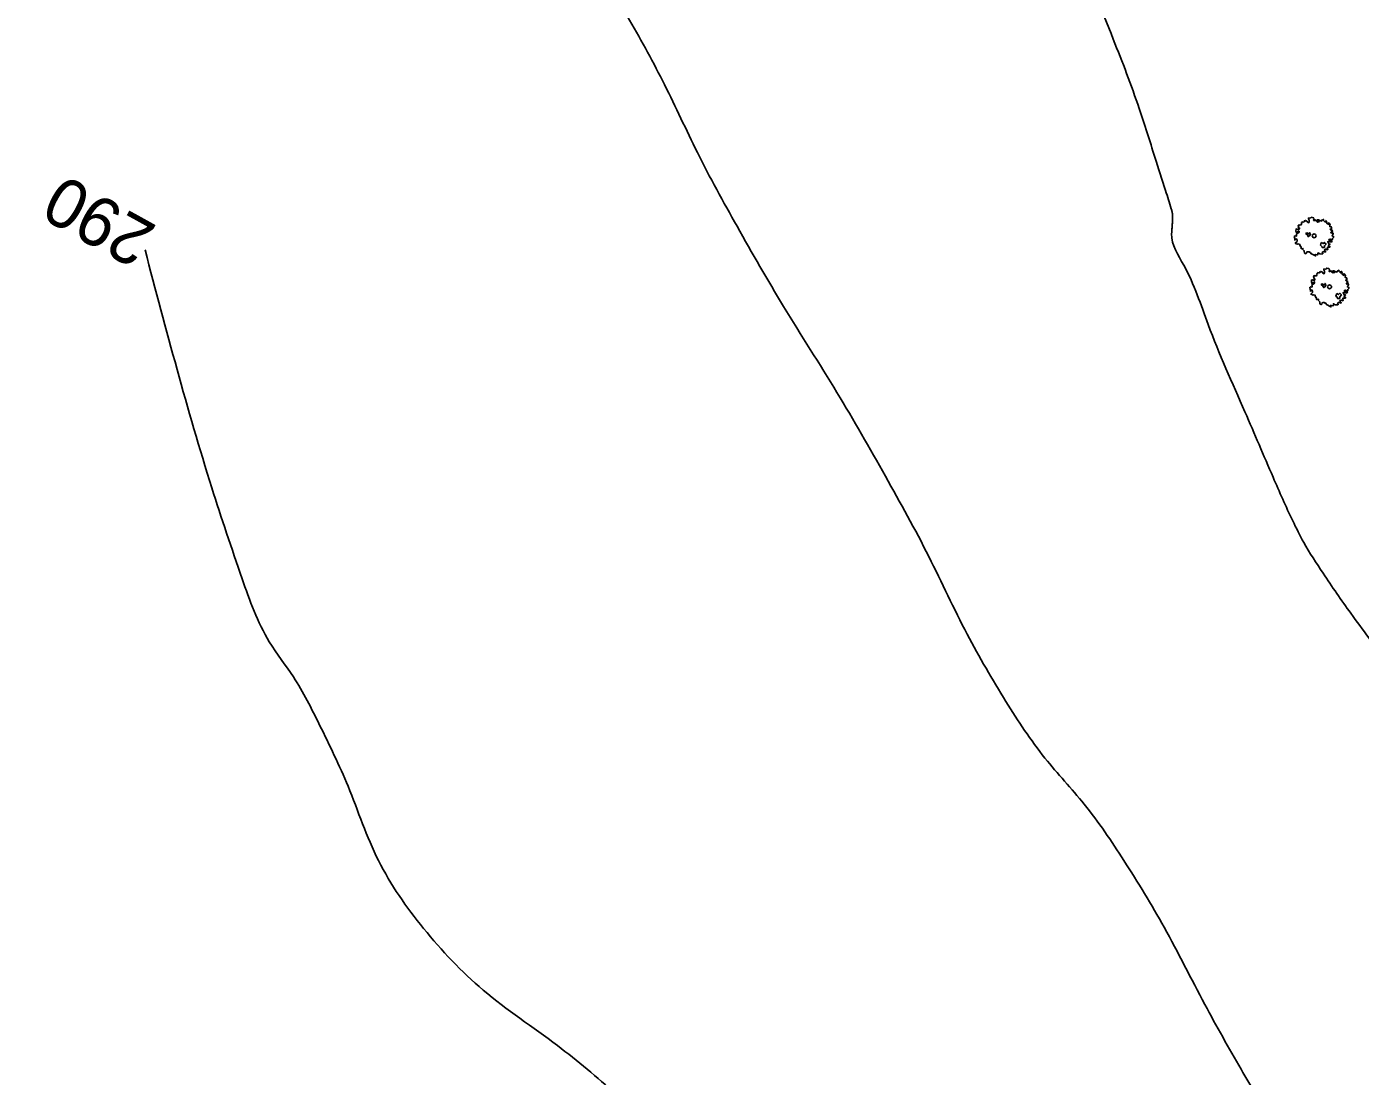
# Model space of a CAD drawing. Extents: x -478464 to -472469, y -1120963 to -1113785.
# Drawn here: x -477489.2 to -477380.7, y -1115869.6 to -1115784.3 of the extents above; entities that cross this region are included whole.
import ezdxf

# ---------------------------------------------------------------- set-up
doc = ezdxf.new("R2010")
doc.units = 0
for name, color, linetype in [('IP', 7, 'Continuous'), ('Vrstevnice_hlavni', 7, 'Continuous'), ('Vrstevnice_popis', 7, 'Continuous'), ('Vrstevnice_vedlejsi', 7, 'Continuous')]:
    doc.layers.add(name, color=color, linetype=linetype)

msp = doc.modelspace()

# ---------------------------------------------------------------- linework, layer by layer
at = {"layer": 'IP'}
for points in [[(-477383.58, -1115800.021), (-477383.485, -1115800.094), (-477383.507, -1115800.177), (-477383.448, -1115800.289), (-477383.314, -1115800.351), (-477383.357, -1115800.241), (-477383.306, -1115800.226), (-477383.191, -1115800.35), (-477383.214, -1115800.343), (-477383.223, -1115800.532), (-477383.106, -1115800.546), (-477383.081, -1115800.628), (-477383.095, -1115800.704), (-477383.162, -1115800.72), (-477383.181, -1115800.765), (-477383.084, -1115800.863), (-477383.07, -1115800.784), (-477383.011, -1115800.875), (-477383.034, -1115800.961), (-477383.133, -1115800.994), (-477383.102, -1115801.054), (-477382.979, -1115801.027), (-477382.944, -1115801.087), (-477382.981, -1115801.174), (-477383.057, -1115801.247), (-477382.921, -1115801.33), (-477382.923, -1115801.408), (-477383.014, -1115801.491), (-477383.005, -1115801.59), (-477383.074, -1115801.606), (-477383.196, -1115801.547), (-477383.289, -1115801.578), (-477383.273, -1115801.68), (-477383.186, -1115801.734), (-477383.193, -1115801.68), (-477383.149, -1115801.656), (-477383.092, -1115801.645), (-477383.045, -1115801.743), (-477383.087, -1115801.8), (-477383.231, -1115801.78), (-477383.281, -1115801.748), (-477383.404, -1115801.765), (-477383.391, -1115801.771), (-477383.301, -1115801.93), (-477383.196, -1115801.944), (-477383.317, -1115802.023), (-477383.293, -1115802.1), (-477383.207, -1115802.136), (-477383.209, -1115802.199), (-477383.418, -1115802.209), (-477383.422, -1115802.312), (-477383.364, -1115802.361), (-477383.469, -1115802.421), (-477383.513, -1115802.357), (-477383.6, -1115802.377), (-477383.653, -1115802.456), (-477383.561, -1115802.551), (-477383.561, -1115802.607), (-477383.647, -1115802.594), (-477383.692, -1115802.564), (-477383.77, -1115802.568), (-477383.839, -1115802.621), (-477383.789, -1115802.723), (-477383.831, -1115802.762), (-477384.03, -1115802.741), (-477384.177, -1115802.662), (-477384.215, -1115802.836), (-477384.349, -1115802.8), (-477384.443, -1115802.811), (-477384.383, -1115802.919), (-477384.753, -1115802.727), (-477384.798, -1115802.623), (-477384.881, -1115802.619), (-477384.898, -1115802.571), (-477385.014, -1115802.569), (-477385.102, -1115802.586), (-477385.121, -1115802.687), (-477385.177, -1115802.732), (-477385.277, -1115802.68), (-477385.297, -1115802.498), (-477385.43, -1115802.369), (-477385.392, -1115802.297), (-477385.549, -1115802.326), (-477385.559, -1115802.169), (-477385.616, -1115802.151), (-477385.657, -1115802.007), (-477385.656, -1115801.973), (-477385.804, -1115801.933), (-477385.847, -1115801.958), (-477385.948, -1115801.92), (-477386.029, -1115801.869), (-477385.878, -1115801.734), (-477385.874, -1115801.627), (-477385.917, -1115801.536), (-477385.987, -1115801.558), (-477386.056, -1115801.64), (-477386.075, -1115801.487), (-477386.113, -1115801.329), (-477386.051, -1115801.273), (-477385.93, -1115801.299), (-477385.918, -1115801.22), (-477385.938, -1115801.123), (-477385.773, -1115801.038), (-477385.71, -1115800.964), (-477385.722, -1115800.904), (-477385.784, -1115800.953), (-477385.858, -1115800.953), (-477385.944, -1115801.007), (-477385.979, -1115800.895), (-477385.969, -1115800.733), (-477385.892, -1115800.702), (-477385.827, -1115800.78), (-477385.757, -1115800.805), (-477385.691, -1115800.67), (-477385.684, -1115800.647), (-477385.784, -1115800.646), (-477385.746, -1115800.571), (-477385.775, -1115800.523), (-477385.803, -1115800.44), (-477385.745, -1115800.374), (-477385.679, -1115800.403), (-477385.564, -1115800.392), (-477385.535, -1115800.303), (-477385.547, -1115800.248), (-477385.446, -1115800.192), (-477385.472, -1115800.132), (-477385.34, -1115800.159), (-477385.282, -1115800.126), (-477385.285, -1115800.059), (-477385.198, -1115800.03), (-477385.189, -1115800.075), (-477385.137, -1115800.071), (-477385.081, -1115800.088), (-477385.059, -1115800.113), (-477385.049, -1115800.155), (-477385.022, -1115800.194), (-477384.987, -1115800.22), (-477384.934, -1115800.205), (-477384.911, -1115800.141), (-477384.91, -1115799.999), (-477384.957, -1115799.89), (-477384.952, -1115799.823), (-477384.835, -1115799.843), (-477384.751, -1115799.814), (-477384.731, -1115799.764), (-477384.557, -1115799.804), (-477384.542, -1115799.847), (-477384.503, -1115799.908), (-477384.538, -1115800.035), (-477384.475, -1115800.04), (-477384.375, -1115799.984), (-477384.312, -1115800.085), (-477384.206, -1115800.155), (-477384.076, -1115800.128), (-477384.239, -1115799.985), (-477384.152, -1115799.977), (-477383.91, -1115800.091), (-477383.858, -1115800.004), (-477383.749, -1115799.94), (-477383.72, -1115799.953), (-477383.751, -1115800.019), (-477383.618, -1115800.15), (-477383.556, -1115800.122)], [(-477385.05, -1115801.13), (-477385.05, -1115801.221), (-477384.967, -1115801.351), (-477384.87, -1115801.289), (-477384.789, -1115801.176), (-477384.867, -1115801.01), (-477384.887, -1115801.122), (-477384.952, -1115801.111), (-477385.014, -1115801.066), (-477385.041, -1115801.047), (-477385.161, -1115801.061), (-477385.154, -1115801.122), (-477385.121, -1115801.17), (-477385.075, -1115801.151)], [(-477383.916, -1115801.825), (-477383.989, -1115802.035), (-477383.822, -1115802.19), (-477383.853, -1115802.224), (-477383.667, -1115802.228), (-477383.664, -1115802.087), (-477383.53, -1115801.945), (-477383.672, -1115801.811), (-477383.774, -1115801.92), (-477383.841, -1115801.857)], [(-477382.326, -1115804.163), (-477382.23, -1115804.236), (-477382.252, -1115804.318), (-477382.194, -1115804.431), (-477382.06, -1115804.492), (-477382.102, -1115804.383), (-477382.052, -1115804.368), (-477381.937, -1115804.492), (-477381.959, -1115804.484), (-477381.968, -1115804.674), (-477381.852, -1115804.687), (-477381.827, -1115804.77), (-477381.841, -1115804.846), (-477381.908, -1115804.862), (-477381.927, -1115804.907), (-477381.83, -1115805.005), (-477381.816, -1115804.926), (-477381.757, -1115805.017), (-477381.78, -1115805.103), (-477381.878, -1115805.135), (-477381.848, -1115805.196), (-477381.724, -1115805.169), (-477381.689, -1115805.229), (-477381.727, -1115805.316), (-477381.802, -1115805.389), (-477381.666, -1115805.471), (-477381.669, -1115805.55), (-477381.76, -1115805.633), (-477381.751, -1115805.732), (-477381.82, -1115805.747), (-477381.942, -1115805.689), (-477382.035, -1115805.72), (-477382.019, -1115805.822), (-477381.931, -1115805.876), (-477381.938, -1115805.822), (-477381.895, -1115805.798), (-477381.837, -1115805.786), (-477381.791, -1115805.884), (-477381.832, -1115805.941), (-477381.977, -1115805.922), (-477382.027, -1115805.89), (-477382.149, -1115805.907), (-477382.136, -1115805.912), (-477382.046, -1115806.072), (-477381.942, -1115806.085), (-477382.062, -1115806.164), (-477382.038, -1115806.242), (-477381.953, -1115806.278), (-477381.955, -1115806.34), (-477382.164, -1115806.351), (-477382.168, -1115806.453), (-477382.11, -1115806.503), (-477382.214, -1115806.563), (-477382.258, -1115806.498), (-477382.346, -1115806.519), (-477382.398, -1115806.598), (-477382.307, -1115806.693), (-477382.306, -1115806.749), (-477382.393, -1115806.736), (-477382.438, -1115806.706), (-477382.516, -1115806.709), (-477382.584, -1115806.763), (-477382.535, -1115806.865), (-477382.577, -1115806.903), (-477382.776, -1115806.882), (-477382.923, -1115806.804), (-477382.961, -1115806.977), (-477383.095, -1115806.942), (-477383.189, -1115806.953), (-477383.129, -1115807.061), (-477383.499, -1115806.869), (-477383.543, -1115806.765), (-477383.626, -1115806.761), (-477383.644, -1115806.713), (-477383.76, -1115806.711), (-477383.848, -1115806.728), (-477383.867, -1115806.828), (-477383.922, -1115806.873), (-477384.022, -1115806.822), (-477384.043, -1115806.64), (-477384.176, -1115806.511), (-477384.138, -1115806.439), (-477384.294, -1115806.467), (-477384.305, -1115806.31), (-477384.362, -1115806.293), (-477384.402, -1115806.149), (-477384.402, -1115806.115), (-477384.55, -1115806.075), (-477384.593, -1115806.1), (-477384.694, -1115806.062), (-477384.775, -1115806.01), (-477384.623, -1115805.876), (-477384.619, -1115805.769), (-477384.663, -1115805.677), (-477384.733, -1115805.7), (-477384.801, -1115805.782), (-477384.821, -1115805.629), (-477384.859, -1115805.47), (-477384.797, -1115805.415), (-477384.676, -1115805.441), (-477384.664, -1115805.361), (-477384.684, -1115805.265), (-477384.519, -1115805.179), (-477384.456, -1115805.106), (-477384.467, -1115805.046), (-477384.53, -1115805.095), (-477384.603, -1115805.095), (-477384.69, -1115805.149), (-477384.725, -1115805.037), (-477384.715, -1115804.875), (-477384.638, -1115804.844), (-477384.572, -1115804.921), (-477384.502, -1115804.947), (-477384.437, -1115804.812), (-477384.43, -1115804.789), (-477384.529, -1115804.788), (-477384.492, -1115804.712), (-477384.521, -1115804.665), (-477384.548, -1115804.582), (-477384.49, -1115804.516), (-477384.424, -1115804.545), (-477384.31, -1115804.534), (-477384.281, -1115804.445), (-477384.293, -1115804.39), (-477384.191, -1115804.333), (-477384.218, -1115804.273), (-477384.086, -1115804.301), (-477384.027, -1115804.268), (-477384.03, -1115804.201), (-477383.944, -1115804.172), (-477383.935, -1115804.217), (-477383.882, -1115804.213), (-477383.826, -1115804.229), (-477383.804, -1115804.254), (-477383.795, -1115804.297), (-477383.768, -1115804.335), (-477383.733, -1115804.362), (-477383.679, -1115804.346), (-477383.656, -1115804.283), (-477383.656, -1115804.141), (-477383.703, -1115804.032), (-477383.697, -1115803.965), (-477383.58, -1115803.985), (-477383.497, -1115803.956), (-477383.477, -1115803.906), (-477383.302, -1115803.945), (-477383.288, -1115803.989), (-477383.248, -1115804.05), (-477383.284, -1115804.176), (-477383.22, -1115804.181), (-477383.12, -1115804.125), (-477383.058, -1115804.227), (-477382.951, -1115804.297), (-477382.821, -1115804.269), (-477382.985, -1115804.126), (-477382.898, -1115804.119), (-477382.656, -1115804.232), (-477382.603, -1115804.146), (-477382.495, -1115804.082), (-477382.466, -1115804.095), (-477382.497, -1115804.161), (-477382.363, -1115804.292), (-477382.302, -1115804.264)], [(-477383.796, -1115805.271), (-477383.796, -1115805.363), (-477383.713, -1115805.492), (-477383.616, -1115805.43), (-477383.534, -1115805.318), (-477383.613, -1115805.151), (-477383.632, -1115805.264), (-477383.698, -1115805.253), (-477383.76, -1115805.208), (-477383.786, -1115805.188), (-477383.907, -1115805.203), (-477383.899, -1115805.263), (-477383.867, -1115805.312), (-477383.821, -1115805.293)], [(-477382.662, -1115805.966), (-477382.735, -1115806.177), (-477382.567, -1115806.331), (-477382.599, -1115806.365), (-477382.413, -1115806.37), (-477382.41, -1115806.229), (-477382.276, -1115806.087), (-477382.418, -1115805.953), (-477382.52, -1115806.061), (-477382.587, -1115805.999)]]:
    msp.add_lwpolyline(points, close=True, dxfattribs=at)
for centre in [(-477384.497, -1115801.283), (-477383.243, -1115805.425)]:
    msp.add_circle(centre, 0.158, dxfattribs=at)
at = {"layer": 'Vrstevnice_hlavni'}
msp.add_spline([(-477334.231, -1115993.767), (-477348.086, -1115974.579), (-477353.101, -1115967.63), (-477356.202, -1115963.324), (-477357.39, -1115961.662), (-477358.34, -1115960.372), (-477359.052, -1115959.453), (-477359.526, -1115958.907), (-477362.084, -1115956.522), (-477366.726, -1115952.3), (-477373.452, -1115946.239), (-477379.296, -1115939.957), (-477384.258, -1115933.452), (-477388.338, -1115926.726), (-477391.356, -1115921.698), (-477393.313, -1115918.368), (-477394.208, -1115916.735), (-477395.349, -1115914.754), (-477396.737, -1115912.425), (-477398.372, -1115909.747), (-477403.163, -1115904.953), (-477411.112, -1115898.043), (-477422.219, -1115889.018), (-477430.365, -1115882.071), (-477435.55, -1115877.203), (-477437.775, -1115874.413), (-477441.27, -1115871.051), (-477446.035, -1115867.117), (-477452.07, -1115862.611), (-477456.921, -1115857.596), (-477460.587, -1115852.07), (-477463.068, -1115846.035), (-477465.376, -1115841.059), (-477467.509, -1115837.142), (-477469.467, -1115834.284), (-477471.678, -1115829.157), (-477474.142, -1115821.76), (-477479.574, -1115802.43)], degree=3, dxfattribs=at)
at = {"layer": 'Vrstevnice_vedlejsi'}
for points in [[(-477535.93, -1115532.82), (-477534.231, -1115534.826), (-477529.55, -1115540.603), (-477524.775, -1115546.882), (-477521.239, -1115551.827), (-477518.943, -1115555.44), (-477517.886, -1115557.72), (-477517.005, -1115559.768), (-477516.301, -1115561.585), (-477515.773, -1115563.17), (-477514.249, -1115568.143), (-477511.731, -1115576.504), (-477508.218, -1115588.252), (-477503.131, -1115599.263), (-477496.47, -1115609.538), (-477488.235, -1115619.076), (-477482.234, -1115626.134), (-477478.468, -1115630.712), (-477476.937, -1115632.811), (-477475.949, -1115634.309), (-477475.506, -1115635.207), (-477475.606, -1115635.504), (-477475.009, -1115636.168), (-477473.714, -1115637.2), (-477471.722, -1115638.6), (-477467.091, -1115642.447), (-477459.82, -1115648.74), (-477449.91, -1115657.48), (-477441.655, -1115664.837), (-477435.056, -1115670.813), (-477430.112, -1115675.407), (-477426.12, -1115679.408), (-477423.08, -1115682.818), (-477420.993, -1115685.636), (-477418.264, -1115689.357), (-477414.894, -1115693.981), (-477410.881, -1115699.507), (-477407.419, -1115704.78), (-477404.507, -1115709.801), (-477402.145, -1115714.569), (-477400.568, -1115717.748), (-477399.774, -1115719.338), (-477399.764, -1115719.338), (-477399.751, -1115719.361), (-477399.735, -1115719.406), (-477399.716, -1115719.475), (-477399.696, -1115719.545), (-477399.675, -1115719.618), (-477399.654, -1115719.693), (-477399.629, -1115719.768), (-477399.599, -1115719.845), (-477399.566, -1115719.922), (-477399.526, -1115720.024), (-477399.48, -1115720.149), (-477399.428, -1115720.299), (-477397.485, -1115724.164), (-477393.652, -1115731.746), (-477387.928, -1115743.044), (-477383.476, -1115752.353), (-477380.296, -1115759.674), (-477378.386, -1115765.008), (-477376.582, -1115770.037), (-477374.882, -1115774.763), (-477373.286, -1115779.185), (-477372.202, -1115782.353), (-477371.628, -1115784.267), (-477371.566, -1115784.927), (-477371.519, -1115785.601), (-477371.488, -1115786.291), (-477371.473, -1115786.997), (-477371.503, -1115787.551), (-477371.579, -1115787.953), (-477371.701, -1115788.205), (-477371.905, -1115788.793), (-477372.19, -1115789.717), (-477372.558, -1115790.978), (-477373.011, -1115792.65), (-477373.549, -1115794.733), (-477374.173, -1115797.226), (-477374.607, -1115798.989), (-477374.851, -1115800.019), (-477374.905, -1115800.319), (-477374.939, -1115800.599), (-477374.955, -1115800.858)], [(-477287.632, -1116051.539), (-477286.32, -1116047.536), (-477285.638, -1116044.105), (-477285.587, -1116041.246), (-477286.167, -1116038.959), (-477287.659, -1116036.397), (-477290.063, -1116033.561), (-477293.379, -1116030.449), (-477295.283, -1116025.963), (-477295.775, -1116020.104), (-477294.854, -1116012.871), (-477293.825, -1116007.495), (-477292.688, -1116003.976), (-477291.442, -1116002.315), (-477290.445, -1115998.859), (-477289.699, -1115993.611), (-477289.202, -1115986.569), (-477288.676, -1115980.878), (-477288.121, -1115976.537), (-477287.537, -1115973.548), (-477287.201, -1115971.521), (-477287.115, -1115970.456), (-477287.276, -1115970.354), (-477288.335, -1115969.099), (-477290.29, -1115966.689), (-477293.142, -1115963.125), (-477296.708, -1115959.125), (-477300.986, -1115954.688), (-477305.978, -1115949.815), (-477309.475, -1115946.392), (-477311.478, -1115944.42), (-477311.987, -1115943.899), (-477313.16, -1115942.38), (-477314.997, -1115939.862), (-477317.498, -1115936.346), (-477320.422, -1115932.577), (-477323.768, -1115928.554), (-477327.536, -1115924.277), (-477331.317, -1115918.9), (-477335.113, -1115912.423), (-477338.922, -1115904.846), (-477342.49, -1115897.876), (-477345.815, -1115891.512), (-477348.9, -1115885.756), (-477351.846, -1115880.306), (-477354.656, -1115875.16), (-477357.328, -1115870.321), (-477360.247, -1115865.399), (-477363.413, -1115860.395), (-477366.825, -1115855.308), (-477369.7, -1115850.782), (-477372.037, -1115846.815), (-477373.837, -1115843.407), (-477376.016, -1115839.798), (-477378.575, -1115835.985), (-477381.514, -1115831.971), (-477383.772, -1115828.71), (-477385.347, -1115826.203), (-477386.24, -1115824.45), (-477387.833, -1115820.914), (-477390.124, -1115815.596), (-477393.114, -1115808.495), (-477395.102, -1115803.67), (-477396.086, -1115801.12), (-477396.068, -1115800.846), (-477396.049, -1115800.554), (-477396.029, -1115800.243), (-477396.007, -1115799.914), (-477396.014, -1115799.611), (-477396.048, -1115799.335), (-477396.111, -1115799.086), (-477396.578, -1115797.601), (-477397.449, -1115794.879), (-477398.725, -1115790.921), (-477400.833, -1115785.286), (-477403.776, -1115777.975), (-477407.552, -1115768.988), (-477412.65, -1115759.156), (-477419.071, -1115748.481), (-477426.814, -1115736.962), (-477432.395, -1115728.678), (-477435.814, -1115723.629), (-477437.071, -1115721.814), (-477437.943, -1115720.536), (-477438.43, -1115719.794), (-477438.532, -1115719.589), (-477438.752, -1115719.242), (-477439.089, -1115718.756), (-477439.545, -1115718.129), (-477443.189, -1115713.546), (-477450.023, -1115705.007), (-477460.046, -1115692.512), (-477467.831, -1115683.216), (-477473.377, -1115677.119), (-477476.685, -1115674.221), (-477481.13, -1115671.048), (-477486.712, -1115667.599)], [(-477337.266, -1115946.887), (-477348.633, -1115933.773), (-477356.25, -1115924.996), (-477360.116, -1115920.556), (-477360.231, -1115920.451), (-477360.332, -1115920.343), (-477360.417, -1115920.231), (-477360.487, -1115920.116), (-477362.086, -1115917.208), (-477365.214, -1115911.509), (-477369.87, -1115903.018), (-477373.961, -1115895.74), (-477377.487, -1115889.676), (-477380.447, -1115884.825), (-477383.162, -1115880.486), (-477385.631, -1115876.66), (-477387.854, -1115873.346), (-477390.44, -1115869.048), (-477393.387, -1115863.766), (-477396.696, -1115857.501), (-477399.966, -1115852.076), (-477403.196, -1115847.491), (-477406.387, -1115843.745), (-477409.557, -1115839.142), (-477412.706, -1115833.68), (-477415.833, -1115827.36), (-477419.365, -1115820.809), (-477423.302, -1115814.027), (-477427.644, -1115807.013), (-477431.429, -1115800.502), (-477434.657, -1115794.492), (-477437.328, -1115788.984), (-477440.163, -1115783.757), (-477443.16, -1115778.81), (-477446.319, -1115774.144), (-477449.256, -1115769.981), (-477451.971, -1115766.319), (-477454.463, -1115763.16), (-477457.329, -1115759.698), (-477460.57, -1115755.933), (-477464.185, -1115751.866), (-477467.95, -1115747.267), (-477471.866, -1115742.136), (-477475.933, -1115736.472), (-477480.254, -1115731.495), (-477484.827, -1115727.205), (-477489.655, -1115723.603), (-477494.56, -1115720.054), (-477499.544, -1115716.559), (-477504.606, -1115713.117), (-477509.129, -1115709.621), (-477513.112, -1115706.071), (-477516.556, -1115702.467), (-477521.43, -1115700.546), (-477527.734, -1115700.309), (-477535.469, -1115701.756), (-477542.487, -1115702.155), (-477548.79, -1115701.506), (-477554.378, -1115699.809), (-477559.514, -1115699.703), (-477564.199, -1115701.187), (-477568.432, -1115704.261), (-477572.401, -1115707.717), (-477576.106, -1115711.556), (-477579.547, -1115715.778), (-477582.875, -1115719.448), (-477586.091, -1115722.567), (-477589.196, -1115725.133), (-477592.121, -1115728.755), (-477594.867, -1115733.431), (-477597.433, -1115739.162), (-477599.711, -1115744.095), (-477601.7, -1115748.229), (-477603.4, -1115751.564), (-477604.536, -1115754.357), (-477605.107, -1115756.608), (-477605.113, -1115758.317), (-477606.183, -1115762.278), (-477608.316, -1115768.491), (-477611.512, -1115776.956), (-477614.039, -1115784.219), (-477615.896, -1115790.281), (-477617.084, -1115795.14), (-477618.243, -1115800.778), (-477619.374, -1115807.193), (-477620.476, -1115814.385), (-477621.656, -1115821.228), (-477622.913, -1115827.72), (-477624.247, -1115833.862), (-477625.523, -1115841.185), (-477626.739, -1115849.689), (-477627.896, -1115859.373), (-477628.764, -1115867.045), (-477629.343, -1115872.705), (-477629.633, -1115876.353), (-477628.131, -1115881.371), (-477624.837, -1115887.759)]]:
    msp.add_spline(points, degree=3, dxfattribs=at)

# ---------------------------------------------------------------- texts
at = {"layer": 'Vrstevnice_popis'}
msp.add_text(' 290 ', height=4, rotation=151.01566, dxfattribs=at).set_placement((-477477.183, -1115801.254))

doc.saveas('drawing.dxf')
